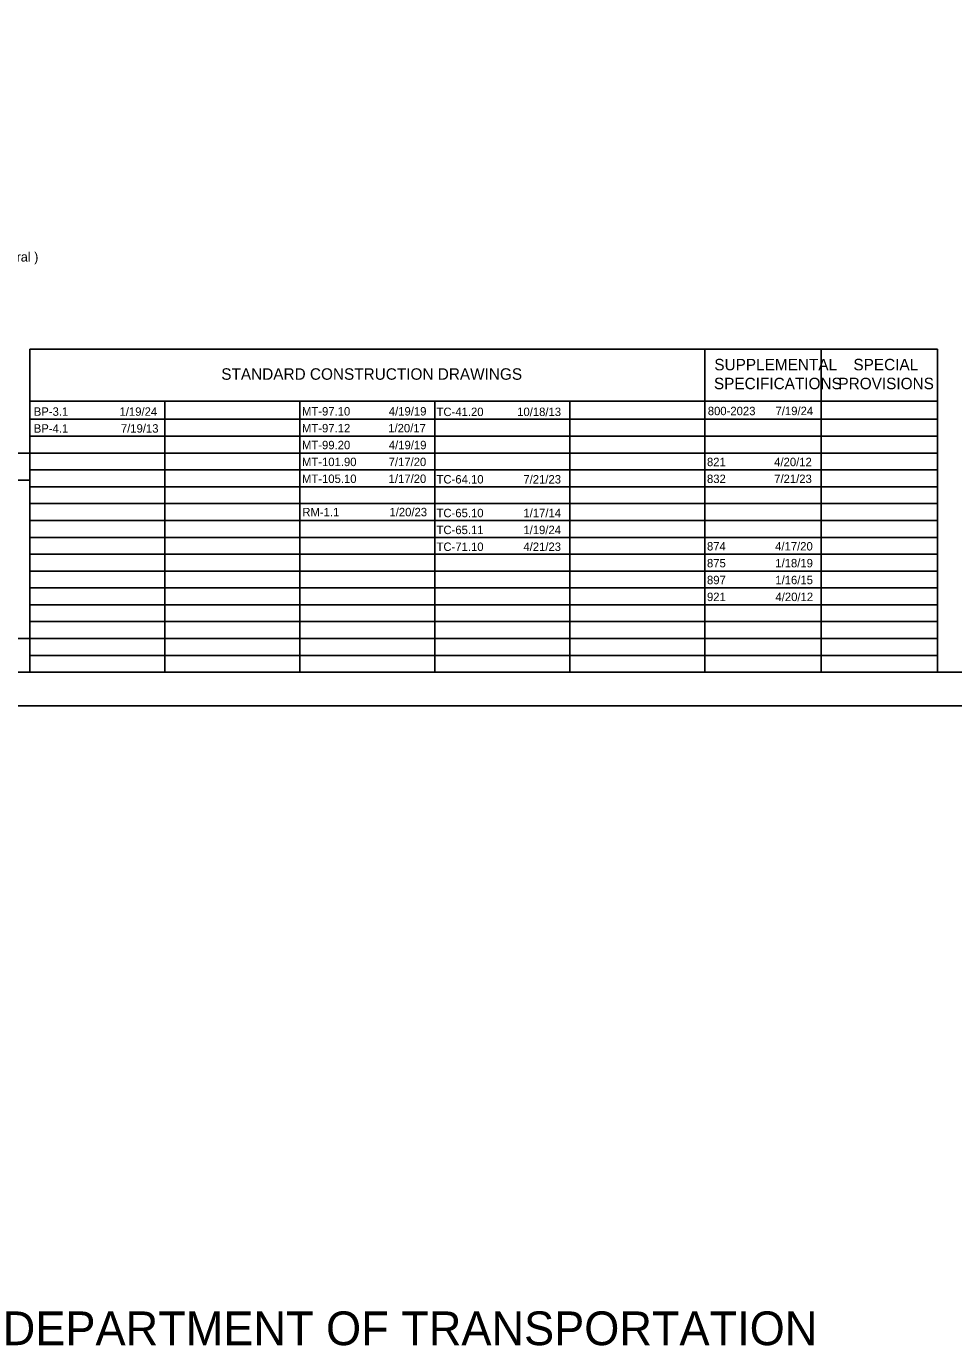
# Model space of a CAD drawing. Extents: x -10.1 to 68, y -9.5 to 29.2.
# Drawn here: x 10.1 to 23.84, y -9.48 to 10.07 of the extents above; entities that cross this region are included whole.
import ezdxf

# ---------------------------------------------------------------- set-up
doc = ezdxf.new("R2010")
doc.units = 0
for name, color, linetype in [('SH_Border', 7, 'Continuous'), ('SH_Cut_Line', 7, 'Continuous'), ('SH_Data', 7, 'Continuous'), ('SH_Text', 7, 'Continuous')]:
    doc.layers.add(name, color=color, linetype=linetype)

msp = doc.modelspace()

# ---------------------------------------------------------------- linework, layer by layer
at = {"layer": 'SH_Border'}
msp.add_lwpolyline([(1.5, 21.5), (33.5, 21.5), (33.5, 0.5), (1.5, 0.5)], close=True, dxfattribs=at)
at = {"layer": 'SH_Cut_Line'}
msp.add_lwpolyline([(0, 0), (34, 0), (34, 22), (0, 22)], close=True, dxfattribs=at)
at = {"layer": 'SH_Data'}
for p, q in [((10.15, 5.292), (23.6, 5.292)), ((10.15, 0.5), (10.15, 5.292)), ((20.15, 0.5), (20.15, 5.292)), ((21.875, 0.5), (21.875, 5.292)), ((23.6, 0.5), (23.6, 5.292)), ((10.15, 4.521), (23.6, 4.521)), ((12.15, 0.5), (12.15, 4.521)), ((14.15, 0.5), (14.15, 4.521)), ((16.15, 0.5), (16.15, 4.521)), ((18.15, 0.5), (18.15, 4.521)), ((10.15, 4.25), (23.6, 4.25)), ((10.15, 4), (23.6, 4)), ((10.15, 3.75), (7.35, 3.75)), ((10.15, 3.75), (23.6, 3.75)), ((10.15, 0.5), (10.15, 3.75)), ((10.15, 3.35), (7.35, 3.35)), ((10.15, 3.5), (23.6, 3.5)), ((10.15, 3.25), (23.6, 3.25)), ((10.15, 3), (23.6, 3)), ((10.15, 2.75), (23.6, 2.75)), ((10.15, 2.5), (23.6, 2.5)), ((10.15, 2.25), (23.6, 2.25)), ((10.15, 2), (23.6, 2)), ((10.15, 1.75), (23.6, 1.75)), ((10.15, 1.5), (23.6, 1.5)), ((10.15, 1.25), (23.6, 1.25)), ((10.15, 1), (23.6, 1)), ((10.15, 0.75), (23.6, 0.75)), ((10.15, 0.5), (7.35, 0.5))]:
    msp.add_line(p, q, dxfattribs=at)
msp.add_lwpolyline([(10.15, 0.5), (10.15, 1), (7.35, 1), (7.35, 0.5)], close=True, dxfattribs=at)

# ---------------------------------------------------------------- texts
at = {"layer": 'SH_Text'}
for s, height, p in [('(NHS Non-Interstate) -                OTHER PRINCIPAL ARTERIAL - (SLM 2.54 - 2.81) - ( NHS Rural )', 0.14, (1.994, 6.588)), ('SUPPLEMENTAL', 0.17, (20.293, 4.976)), ('SPECIAL', 0.17, (22.354, 4.976)), ('STANDARD CONSTRUCTION DRAWINGS', 0.17, (12.986, 4.836)), ('SPECIFICATIONS', 0.17, (20.287, 4.696)), ('PROVISIONS', 0.17, (22.132, 4.696)), ('BP-3.1', 0.125, (10.207, 4.302)), ('1/19/24', 0.125, (11.478, 4.302)), ('MT-97.10', 0.125, (14.182, 4.306)), ('4/19/19', 0.125, (15.469, 4.306)), ('TC-41.20', 0.125, (16.176, 4.298)), ('10/18/13', 0.125, (17.371, 4.298)), ('800-2023', 0.125, (20.196, 4.311)), ('7/19/24', 0.125, (21.2, 4.312)), ('BP-4.1', 0.125, (10.207, 4.052)), ('7/19/13', 0.125, (11.498, 4.052)), ('MT-97.12', 0.125, (14.182, 4.056)), ('1/20/17', 0.125, (15.46, 4.056)), ('MT-99.20', 0.125, (14.182, 3.806)), ('4/19/19', 0.125, (15.469, 3.806)), ('MT-101.90', 0.125, (14.182, 3.556)), ('7/17/20', 0.125, (15.466, 3.556)), ('821', 0.125, (20.184, 3.555)), ('4/20/12', 0.125, (21.18, 3.555)), ('MT-105.10', 0.125, (14.182, 3.306)), ('1/17/20', 0.125, (15.466, 3.306)), ('TC-64.10', 0.125, (16.176, 3.298)), ('7/21/23', 0.125, (17.463, 3.298)), ('832', 0.125, (20.184, 3.305)), ('7/21/23', 0.125, (21.18, 3.305)), ('RM-1.1', 0.125, (14.187, 2.812)), ('1/20/23', 0.125, (15.478, 2.812)), ('TC-65.10', 0.125, (16.176, 2.798)), ('1/17/14', 0.125, (17.463, 2.798)), ('TC-65.11', 0.125, (16.176, 2.548)), ('1/19/24', 0.125, (17.463, 2.548)), ('TC-71.10', 0.125, (16.176, 2.298)), ('4/21/23', 0.125, (17.463, 2.298)), ('874', 0.125, (20.184, 2.305)), ('4/17/20', 0.125, (21.194, 2.305)), ('875', 0.125, (20.184, 2.055)), ('1/18/19', 0.125, (21.196, 2.055)), ('897', 0.125, (20.184, 1.805)), ('1/16/15', 0.125, (21.197, 1.805)), ('921', 0.125, (20.184, 1.555)), ('4/20/12', 0.125, (21.199, 1.555)), ('DEPARTMENT OF TRANSPORTATION', 0.5, (9.747, -9.476))]:
    msp.add_text(s, height=height, dxfattribs=at).set_placement(p)

doc.saveas('drawing.dxf')
